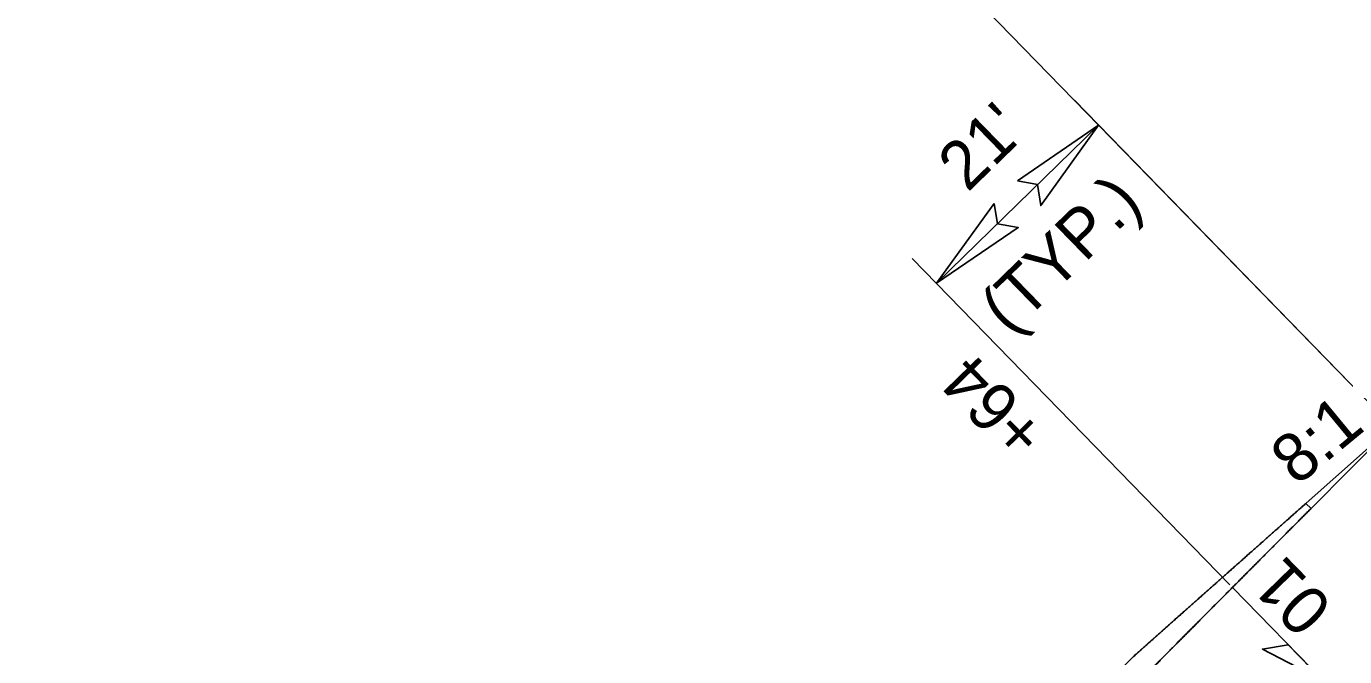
# Model space of a CAD drawing. Extents: x 1183930 to 1185370, y 573068 to 574871.
# Drawn here: x 1184760.3 to 1184882.5, y 574494.7 to 574553.1 of the extents above; entities that cross this region are included whole.
import ezdxf

# ---------------------------------------------------------------- set-up
doc = ezdxf.new("R2010")
doc.units = 0
for name, color, linetype in [('E_NCDOT_Vertical_Profile_Ground_Line', 7, 'Continuous'), ('P_NCDOT_Horizontal_Alignment', 7, 'Continuous'), ('PC_COLUMN', 7, 'Continuous'), ('PC_OBJECT', 7, 'Continuous'), ('PC_PADFOOTING', 7, 'Continuous'), ('PC_SLAB', 7, 'Continuous'), ('PS_HATCH', 7, 'Continuous')]:
    doc.layers.add(name, color=color, linetype=linetype)

msp = doc.modelspace()

# ---------------------------------------------------------------- linework, layer by layer
for points in [[(1184852.17, 574538.79), (1184859.7, 574543.96), (1184854.34, 574536.5), (1184854.04, 574538.45)], [(1184850.02, 574536.69), (1184844.65, 574529.31), (1184852.25, 574534.47), (1184850.31, 574534.82)]]:
    msp.add_lwpolyline(points, close=True)
at = {"layer": 'E_NCDOT_Vertical_Profile_Ground_Line'}
msp.add_line((1184867.9, 574499.11), (1184886.93, 574515.99), dxfattribs=at)
msp.add_line((1184867.9, 574499.11), (1184886.93, 574515.99), dxfattribs=at)
for points in [[(1184862.94, 574494.69), (1184862.98, 574494.73), (1184863.15, 574494.88), (1184863.44, 574495.14), (1184863.68, 574495.35), (1184863.93, 574495.58), (1184864.18, 574495.8), (1184864.42, 574496.02), (1184864.67, 574496.24), (1184864.92, 574496.46), (1184865.17, 574496.68), (1184865.42, 574496.9), (1184865.66, 574497.12), (1184865.91, 574497.34), (1184866.16, 574497.56), (1184866.41, 574497.79), (1184866.66, 574498.01), (1184866.9, 574498.23), (1184867.16, 574498.45), (1184867.39, 574498.66), (1184867.69, 574498.92), (1184867.85, 574499.07), (1184867.9, 574499.11)], [(1184862.94, 574494.69), (1184862.98, 574494.73), (1184863.15, 574494.88), (1184863.44, 574495.14), (1184863.68, 574495.35), (1184863.93, 574495.58), (1184864.18, 574495.8), (1184864.42, 574496.02), (1184864.67, 574496.24), (1184864.92, 574496.46), (1184865.17, 574496.68), (1184865.42, 574496.9), (1184865.66, 574497.12), (1184865.91, 574497.34), (1184866.16, 574497.56), (1184866.41, 574497.79), (1184866.66, 574498.01), (1184866.9, 574498.23), (1184867.16, 574498.45), (1184867.39, 574498.66), (1184867.69, 574498.92), (1184867.85, 574499.07), (1184867.9, 574499.11)], [(1184862.93, 574494.68), (1184862.93, 574494.69), (1184862.93, 574494.69), (1184862.94, 574494.69)], [(1184862.93, 574494.68), (1184862.93, 574494.69), (1184862.93, 574494.69), (1184862.94, 574494.69)]]:
    msp.add_open_spline(points, degree=2, dxfattribs=at)
at = {"layer": 'P_NCDOT_Horizontal_Alignment'}
msp.add_line((1184869.02, 574497.99), (1184886.93, 574515.99), dxfattribs=at)
msp.add_line((1184869.02, 574497.99), (1184886.93, 574515.99), dxfattribs=at)
msp.add_open_spline([(1184864.34, 574493.26), (1184864.41, 574493.34), (1184864.57, 574493.5), (1184864.8, 574493.74), (1184865.04, 574493.97), (1184865.27, 574494.21), (1184865.51, 574494.45), (1184865.74, 574494.68), (1184865.97, 574494.92), (1184866.21, 574495.16), (1184866.44, 574495.39), (1184866.68, 574495.63), (1184866.91, 574495.86), (1184867.15, 574496.1), (1184867.38, 574496.34), (1184867.62, 574496.57), (1184867.85, 574496.81), (1184868.08, 574497.05), (1184868.32, 574497.28), (1184868.55, 574497.52), (1184868.79, 574497.75), (1184868.95, 574497.91), (1184869.02, 574497.99)], degree=3, dxfattribs=at)
msp.add_open_spline([(1184864.34, 574493.26), (1184864.41, 574493.34), (1184864.57, 574493.5), (1184864.8, 574493.74), (1184865.04, 574493.97), (1184865.27, 574494.21), (1184865.51, 574494.45), (1184865.74, 574494.68), (1184865.97, 574494.92), (1184866.21, 574495.16), (1184866.44, 574495.39), (1184866.68, 574495.63), (1184866.91, 574495.86), (1184867.15, 574496.1), (1184867.38, 574496.34), (1184867.62, 574496.57), (1184867.85, 574496.81), (1184868.08, 574497.05), (1184868.32, 574497.28), (1184868.55, 574497.52), (1184868.79, 574497.75), (1184868.95, 574497.91), (1184869.02, 574497.99)], degree=3, dxfattribs=at)
at = {"layer": 'PC_COLUMN'}
msp.add_lwpolyline([(1184880.51, 574492.47), (1184874.89, 574495.38), (1184877.28, 574495.78)], close=True, dxfattribs=at)
at = {"layer": 'PC_OBJECT'}
msp.add_lwpolyline([(1184879.4, 574508.42), (1184878.93, 574508.89)], dxfattribs=at)
msp.add_arc((1186063.32, 573271.23), 1714, 134.45454, 136.36856, dxfattribs=at)
for points in [[(1184878.93, 574508.89), (1184878.84, 574508.81), (1184878.51, 574508.52), (1184878.19, 574508.24), (1184877.87, 574507.95), (1184877.54, 574507.66), (1184877.22, 574507.37), (1184876.89, 574507.09), (1184876.57, 574506.8), (1184876.25, 574506.51), (1184875.92, 574506.23), (1184875.6, 574505.94), (1184875.27, 574505.65), (1184874.95, 574505.36), (1184874.63, 574505.08), (1184874.3, 574504.79), (1184873.98, 574504.5), (1184873.65, 574504.22), (1184873.33, 574503.93), (1184873.01, 574503.64), (1184872.68, 574503.35), (1184872.36, 574503.07), (1184872.04, 574502.78), (1184871.71, 574502.49), (1184871.39, 574502.2), (1184871.06, 574501.92), (1184870.93, 574501.8)], [(1184871.86, 574500.84), (1184871.99, 574500.97), (1184872.29, 574501.28), (1184872.6, 574501.58), (1184872.9, 574501.89), (1184873.21, 574502.19), (1184873.51, 574502.5), (1184873.82, 574502.81), (1184874.12, 574503.11), (1184874.43, 574503.42), (1184874.73, 574503.73), (1184875.04, 574504.03), (1184875.34, 574504.34), (1184875.65, 574504.65), (1184875.95, 574504.95), (1184876.26, 574505.26), (1184876.56, 574505.57), (1184876.87, 574505.87), (1184877.17, 574506.18), (1184877.48, 574506.49), (1184877.78, 574506.79), (1184878.09, 574507.1), (1184878.39, 574507.41), (1184878.7, 574507.71), (1184879, 574508.02), (1184879.31, 574508.33), (1184879.4, 574508.42)], [(1184870.93, 574501.8), (1184870.74, 574501.63), (1184870.42, 574501.34), (1184870.09, 574501.06), (1184869.77, 574500.77), (1184869.44, 574500.48), (1184869.12, 574500.19), (1184868.8, 574499.91), (1184868.47, 574499.62), (1184868.15, 574499.33), (1184867.82, 574499.04), (1184867.5, 574498.75), (1184867.17, 574498.47), (1184866.84, 574498.18), (1184866.52, 574497.89), (1184866.19, 574497.6), (1184865.87, 574497.31), (1184865.54, 574497.01), (1184865.21, 574496.72), (1184864.89, 574496.43), (1184864.56, 574496.14), (1184864.24, 574495.85), (1184863.91, 574495.56), (1184863.59, 574495.27), (1184863.26, 574494.98), (1184862.94, 574494.69)], [(1184864.34, 574493.26), (1184864.64, 574493.57), (1184864.95, 574493.88), (1184865.26, 574494.19), (1184865.56, 574494.5), (1184865.87, 574494.81), (1184866.17, 574495.12), (1184866.48, 574495.43), (1184866.79, 574495.74), (1184867.09, 574496.05), (1184867.4, 574496.36), (1184867.71, 574496.67), (1184868.01, 574496.98), (1184868.32, 574497.28), (1184868.63, 574497.59), (1184868.94, 574497.9), (1184869.24, 574498.21), (1184869.55, 574498.52), (1184869.85, 574498.82), (1184870.16, 574499.13), (1184870.46, 574499.44), (1184870.77, 574499.74), (1184871.07, 574500.05), (1184871.38, 574500.36), (1184871.68, 574500.66), (1184871.86, 574500.84)]]:
    msp.add_spline(points, degree=3, dxfattribs=at)
at = {"layer": 'PC_PADFOOTING'}
for p, q in [((1184886.93, 574515.99), (1184857.46, 574546.27)), ((1184844.65, 574529.31), (1184859.7, 574543.96)), ((1184871.88, 574501.33), (1184842.41, 574531.61))]:
    msp.add_line(p, q, dxfattribs=at)
at = {"layer": 'PC_SLAB'}
msp.add_line((1184872.12, 574501.1), (1184880.61, 574492.38), dxfattribs=at)
at = {"layer": 'PS_HATCH'}
msp.add_line((1184760.25, 574646.12), (1184895.5, 574507.19), dxfattribs=at)

# ---------------------------------------------------------------- texts
at = {"layer": 'PC_PADFOOTING'}
for s, rotation, p in [("21'", 44.2318, (1184847.55, 574537.67)), ('(TYP.)', 44.2318, (1184851.47, 574524.39)), ('+64', 134.2318, (1184855.13, 574515.65)), ('8:1', 39.532, (1184878.09, 574510.43))]:
    msp.add_text(s, height=4.5, rotation=rotation, dxfattribs=at).set_placement(p)
at = {"layer": 'PC_SLAB'}
msp.add_text('01', height=4.5, rotation=134.2318, dxfattribs=at).set_placement((1184881.59, 574499.36))

doc.saveas('drawing.dxf')
